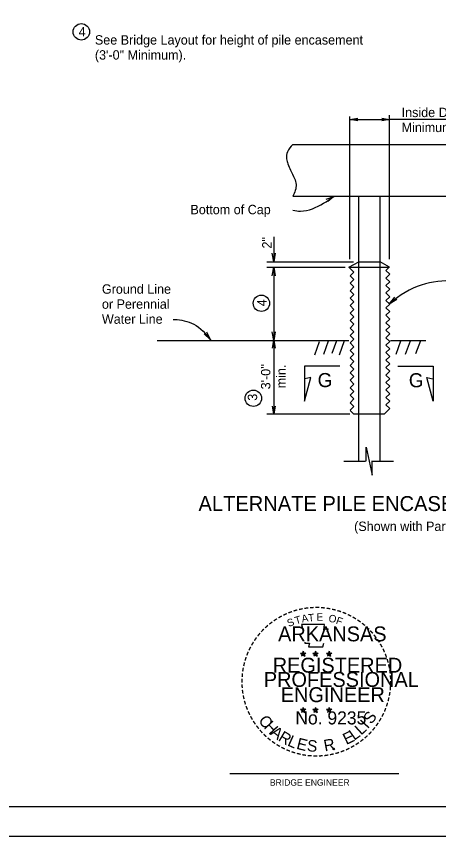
# Model space of a CAD drawing. Extents: x 1053 to 1311, y 5085 to 5337.
# Drawn here: x 1163.9 to 1193.9, y 5085.1 to 5143.4 of the extents above; entities that cross this region are included whole.
import ezdxf

# ---------------------------------------------------------------- set-up
doc = ezdxf.new("R2010")
doc.units = 0
for name, color, linetype in [('1', 7, 'Continuous'), ('2', 7, 'Continuous'), ('7', 7, 'Continuous'), ('9', 7, 'Continuous'), ('B_Border', 7, 'Continuous'), ('B_No_Plot', 7, 'Continuous')]:
    doc.layers.add(name, color=color, linetype=linetype)

msp = doc.modelspace()

# ---------------------------------------------------------------- linework, layer by layer
at = {"layer": '1'}
for p, q in [((1187.562, 5126.114), (1187.562, 5136.252)), ((1187.562, 5136.018), (1190.359, 5136.018)), ((1190.359, 5126.114), (1190.359, 5136.336)), ((1183.514, 5134.241), (1196.697, 5134.241)), ((1183.514, 5130.568), (1196.697, 5130.568)), ((1182.153, 5127.697), (1182.153, 5125.906)), ((1181.658, 5125.906), (1187.801, 5125.906)), ((1181.658, 5125.542), (1187.211, 5125.542)), ((1182.153, 5125.542), (1182.153, 5120.331)), ((1182.162, 5125.496), (1182.162, 5120.286)), ((1182.153, 5120.331), (1182.153, 5115.121)), ((1185.063, 5119.306), (1185.405, 5120.246)), ((1185.704, 5119.349), (1186.046, 5120.289)), ((1186.302, 5119.434), (1186.623, 5120.317)), ((1186.814, 5119.306), (1187.181, 5120.314)), ((1190.829, 5119.349), (1191.171, 5120.289)), ((1191.512, 5119.349), (1191.854, 5120.289)), ((1192.238, 5119.392), (1192.58, 5120.331)), ((1186.834, 5118.507), (1184.334, 5118.507)), ((1184.334, 5118.507), (1184.334, 5116.007)), ((1190.969, 5118.507), (1193.469, 5118.507)), ((1193.469, 5118.507), (1193.469, 5116.007)), ((1184.334, 5116.007), (1184.787, 5117.697)), ((1184.787, 5117.697), (1184.354, 5117.593)), ((1193.469, 5116.007), (1193.016, 5117.697)), ((1193.016, 5117.697), (1193.449, 5117.593)), ((1181.658, 5115.121), (1187.559, 5115.121)), ((1187.806, 5115.121), (1190.017, 5115.121)), ((1188.2, 5111.756), (1188.2, 5115.073)), ((1189.7, 5111.756), (1189.7, 5115.158)), ((1188.699, 5111.742), (1188.699, 5112.742)), ((1188.699, 5112.742), (1189.126, 5110.759)), ((1187.135, 5111.756), (1188.656, 5111.756)), ((1189.083, 5111.756), (1190.658, 5111.756)), ((1189.126, 5110.759), (1189.126, 5111.759)), ((1179.033, 5089.563), (1191.033, 5089.563)), ((1229.529, 5087.179), (1060.921, 5087.179))]:
    msp.add_line(p, q, dxfattribs=at)
for points in [[(1188.109, 5135.922), (1187.562, 5136.018), (1188.109, 5136.115)], [(1189.812, 5136.115), (1190.359, 5136.018), (1189.812, 5135.922)], [(1185.882, 5130.364), (1186.404, 5130.553), (1185.978, 5130.197)], [(1182.262, 5126.522), (1182.153, 5125.906), (1182.045, 5126.522)], [(1182.045, 5124.926), (1182.153, 5125.542), (1182.262, 5124.926)], [(1182.045, 5124.926), (1182.153, 5125.542), (1182.262, 5124.926)], [(1190.878, 5123.229), (1190.346, 5122.902), (1190.734, 5123.392)], [(1177.385, 5120.931), (1177.651, 5120.366), (1177.208, 5120.806)], [(1182.262, 5120.947), (1182.153, 5120.331), (1182.045, 5120.947)], [(1182.057, 5119.784), (1182.153, 5120.331), (1182.25, 5119.784)], [(1182.25, 5115.668), (1182.153, 5115.121), (1182.057, 5115.668)]]:
    msp.add_lwpolyline(points, dxfattribs=at)
for centre in [(1168.493, 5142.256), (1181.274, 5122.967), (1180.703, 5116.22)]:
    msp.add_circle(centre, 0.583, dxfattribs=at)
for points in [[(1183.514, 5134.241), (1183.123, 5133.738), (1183.067, 5133.235), (1183.151, 5132.872), (1183.346, 5132.425), (1183.625, 5131.838), (1183.737, 5131.419), (1183.514, 5130.568)], [(1183.5, 5129.575), (1184.058, 5129.519), (1184.896, 5129.686), (1186.404, 5130.553)]]:
    msp.add_spline(points, degree=3, dxfattribs=at)
at = {"layer": '2'}
msp.add_line((1199.814, 5136.018), (1190.359, 5136.018), dxfattribs=at)
at = {"layer": '7'}
for p, q in [((1188.2, 5125.906), (1188.2, 5130.568)), ((1189.7, 5125.906), (1189.7, 5130.568)), ((1187.475, 5125.542), (1188.201, 5125.906)), ((1187.475, 5125.542), (1190.36, 5125.542)), ((1188.2, 5115.073), (1188.2, 5125.906)), ((1188.201, 5125.906), (1189.701, 5125.906)), ((1189.7, 5115.158), (1189.7, 5125.906)), ((1190.36, 5125.542), (1189.701, 5125.906)), ((1173.886, 5120.331), (1187.478, 5120.331)), ((1190.444, 5120.331), (1192.944, 5120.331))]:
    msp.add_line(p, q, dxfattribs=at)
for points in [[(1187.566, 5124.92), (1187.831, 5125.185), (1187.475, 5125.542)], [(1190.113, 5125.294), (1190.347, 5125.527)], [(1187.566, 5124.39), (1187.831, 5124.655), (1187.566, 5124.92)], [(1190.113, 5124.763), (1190.379, 5125.029), (1190.113, 5125.294)], [(1187.566, 5123.859), (1187.831, 5124.125), (1187.566, 5124.39)], [(1190.113, 5124.233), (1190.379, 5124.498), (1190.113, 5124.763)], [(1187.566, 5123.329), (1187.831, 5123.594), (1187.566, 5123.859)], [(1190.113, 5123.703), (1190.379, 5123.968), (1190.113, 5124.233)], [(1190.113, 5123.172), (1190.379, 5123.437), (1190.113, 5123.703)], [(1187.566, 5122.799), (1187.831, 5123.064), (1187.566, 5123.329)], [(1190.113, 5122.642), (1190.379, 5122.907), (1190.113, 5123.172)], [(1187.566, 5122.268), (1187.831, 5122.534), (1187.566, 5122.799)], [(1190.113, 5122.112), (1190.379, 5122.377), (1190.113, 5122.642)], [(1187.566, 5121.738), (1187.831, 5122.003), (1187.566, 5122.268)], [(1190.113, 5121.581), (1190.379, 5121.846), (1190.113, 5122.112)], [(1187.566, 5121.208), (1187.831, 5121.473), (1187.566, 5121.738)], [(1190.113, 5121.051), (1190.379, 5121.316), (1190.113, 5121.581)], [(1187.566, 5120.677), (1187.831, 5120.943), (1187.566, 5121.208)], [(1190.113, 5120.521), (1190.379, 5120.786), (1190.113, 5121.051)], [(1187.566, 5120.147), (1187.831, 5120.412), (1187.566, 5120.677)], [(1190.113, 5119.99), (1190.379, 5120.255), (1190.113, 5120.521)], [(1187.566, 5119.617), (1187.831, 5119.882), (1187.566, 5120.147)], [(1190.113, 5119.46), (1190.379, 5119.725), (1190.113, 5119.99)], [(1187.566, 5119.086), (1187.831, 5119.352), (1187.566, 5119.617)], [(1187.566, 5118.556), (1187.831, 5118.821), (1187.566, 5119.086)], [(1190.113, 5118.93), (1190.379, 5119.195), (1190.113, 5119.46)], [(1187.566, 5118.026), (1187.831, 5118.291), (1187.566, 5118.556)], [(1190.113, 5118.399), (1190.379, 5118.664), (1190.113, 5118.93)], [(1187.566, 5117.495), (1187.831, 5117.761), (1187.566, 5118.026)], [(1190.113, 5117.869), (1190.379, 5118.134), (1190.113, 5118.399)], [(1187.566, 5116.965), (1187.831, 5117.23), (1187.566, 5117.495)], [(1190.113, 5117.339), (1190.379, 5117.604), (1190.113, 5117.869)], [(1190.113, 5116.808), (1190.379, 5117.073), (1190.113, 5117.339)], [(1187.566, 5116.435), (1187.831, 5116.7), (1187.566, 5116.965)], [(1190.113, 5116.278), (1190.379, 5116.543), (1190.113, 5116.808)], [(1187.566, 5115.904), (1187.831, 5116.17), (1187.566, 5116.435)], [(1190.113, 5115.748), (1190.379, 5116.013), (1190.113, 5116.278)], [(1187.566, 5115.374), (1187.831, 5115.639), (1187.566, 5115.904)], [(1190.017, 5115.121), (1190.379, 5115.482), (1190.113, 5115.748)], [(1187.806, 5115.121), (1187.576, 5115.35)]]:
    msp.add_lwpolyline(points, dxfattribs=at)
for points in [[(1194.915, 5124.574), (1194.211, 5124.598), (1192.57, 5124.406), (1191.128, 5123.597), (1190.346, 5122.902)], [(1175.021, 5121.821), (1175.365, 5121.826), (1176.365, 5121.679), (1177.183, 5121.031), (1177.651, 5120.366)]]:
    msp.add_open_spline(points, degree=3, dxfattribs=at)
at = {"layer": 'B_Border'}
for p, q in [((1184.046, 5098.113), (1184.35, 5097.889)), ((1184.046, 5098.113), (1184.425, 5098.113)), ((1184.238, 5098.246), (1184.121, 5097.889)), ((1184.425, 5098.113), (1184.121, 5097.889)), ((1184.238, 5098.246), (1184.35, 5097.889)), ((1184.932, 5098.113), (1185.236, 5097.889)), ((1184.932, 5098.113), (1185.31, 5098.113)), ((1185.124, 5098.246), (1185.006, 5097.889)), ((1185.31, 5098.113), (1185.006, 5097.889)), ((1185.124, 5098.246), (1185.236, 5097.889)), ((1185.886, 5098.113), (1186.19, 5097.889)), ((1185.886, 5098.113), (1186.265, 5098.113)), ((1186.078, 5098.246), (1185.961, 5097.889)), ((1186.265, 5098.113), (1185.961, 5097.889)), ((1186.078, 5098.246), (1186.19, 5097.889)), ((1184.046, 5094.118), (1184.35, 5093.894)), ((1184.046, 5094.118), (1184.425, 5094.118)), ((1184.238, 5094.251), (1184.121, 5093.894)), ((1184.425, 5094.118), (1184.121, 5093.894)), ((1184.238, 5094.251), (1184.35, 5093.894)), ((1184.932, 5094.118), (1185.236, 5093.894)), ((1184.932, 5094.118), (1185.31, 5094.118)), ((1185.124, 5094.251), (1185.006, 5093.894)), ((1185.31, 5094.118), (1185.006, 5093.894)), ((1185.124, 5094.251), (1185.236, 5093.894)), ((1185.886, 5094.118), (1186.19, 5093.894)), ((1185.886, 5094.118), (1186.265, 5094.118)), ((1186.078, 5094.251), (1185.961, 5093.894)), ((1186.265, 5094.118), (1185.961, 5093.894)), ((1186.078, 5094.251), (1186.19, 5093.894))]:
    msp.add_line(p, q, dxfattribs=at)
for points in [[(1184.11, 5100.15), (1184.238, 5099.707)], [(1185.95, 5099.643), (1186.014, 5099.835), (1185.694, 5099.771), (1185.758, 5100.15), (1184.11, 5100.15)], [(1184.361, 5098.881), (1184.361, 5098.817), (1184.681, 5098.817), (1184.617, 5098.566), (1185.63, 5098.566), (1185.694, 5098.817)]]:
    msp.add_lwpolyline(points, dxfattribs=at)
msp.add_circle((1186.412, 5091.29), 0.0503, dxfattribs=at)
for centre, radius, start, end in [((1186.407, 5091.29), 0.0483, 278.17502, 85.49463), ((1186.392, 5091.289), 0.0518, 294.00117, 69.66848)]:
    msp.add_arc(centre, radius, start, end, dxfattribs=at)
at = {"layer": 'B_No_Plot'}
msp.add_lwpolyline([(1053.308, 5198.862), (1231.974, 5198.862), (1231.974, 5085.07), (1053.308, 5085.07)], close=True, dxfattribs=at)

# ---------------------------------------------------------------- texts
at = {"layer": '1'}
for s, height, p in [('4', 0.667, (1168.302, 5141.931)), ('Bottom of Cap', 0.66667, (1176.237, 5129.295)), ('Ground Line ', 0.66658, (1169.953, 5123.646)), ('or Perennial  ', 0.66658, (1169.953, 5122.579)), ('Water Line', 0.6666, (1169.953, 5121.512)), ('G', 1, (1185.265, 5117.011)), ('G', 1, (1191.737, 5116.999)), ('BRIDGE ENGINEER', 0.45328, (1181.881, 5088.688))]:
    msp.add_text(s, height=height, dxfattribs=at).set_placement(p)
for s, height, p in [('2"', 0.6666, (1181.993, 5126.859)), ('4', 0.667, (1181.636, 5122.755)), ("3'-0''", 0.6666, (1181.912, 5116.851)), ('min.', 0.6667, (1183.002, 5116.922)), ('3', 0.667, (1180.973, 5116.044))]:
    msp.add_text(s, height=height, rotation=90, dxfattribs=at).set_placement(p)
at = {"layer": '7'}
for s, height, p in [('See Bridge Layout for height of pile encasement ', 0.66667, (1169.455, 5141.35)), ('(3\'-0" Minimum).', 0.66667, (1169.455, 5140.283)), ('ALTERNATE PILE ENCASEMENT DETAIL FOR STEEL SHELL PILES', 1.067, (1176.807, 5108.201)), ('(Shown with Partial   Height Encasement)', 0.66658, (1187.856, 5106.787))]:
    msp.add_text(s, height=height, dxfattribs=at).set_placement(p)
at = {"layer": '9'}
for s, p in [('Inside Diameter', (1191.228, 5136.199)), ("Minimum = ''D'' + 8''", (1191.228, 5135.133))]:
    msp.add_text(s, height=0.66667, dxfattribs=at).set_placement(p)
at = {"layer": 'B_Border'}
for s, height, rotation, p in [('-', 0.842, 21.4285, (1183.257, 5100.641)), ('-', 0.842, 17.1428, (1183.604, 5100.774)), ('-', 0.843, 12.8571, (1183.961, 5100.875)), ('-', 0.843, 8.5714, (1184.324, 5100.955)), ('-', 0.843, 4.2857, (1184.692, 5101.003)), ('-', 0.843, 355.7131, (1185.428, 5101.019)), ('-', 0.843, 351.4274, (1185.801, 5100.987)), ('-', 0.843, 347.1417, (1186.164, 5100.923)), ('-', 0.843, 342.856, (1186.521, 5100.838)), ('-', 0.843, 338.5703, (1186.878, 5100.726)), ('-', 0.843, 34.2856, (1182.292, 5100.102)), ('-', 0.843, 29.9999, (1182.601, 5100.305)), ('-', 0.843, 25.7142, (1182.921, 5100.486)), ('S', 0.528, 21.59401, (1183.22, 5099.958)), ('T', 0.528, 16.4036, (1183.726, 5100.15)), ('A', 0.529, 11.21318, (1184.174, 5100.278)), ('T', 0.529, 6.02276, (1184.617, 5100.342)), ('E', 0.529, 0.83234, (1185.188, 5100.406)), ('O', 0.528, 350.4515, (1186.014, 5100.342)), ('F', 0.528, 340.07066, (1186.521, 5100.214)), ('-', 0.843, 334.2846, (1187.22, 5100.582)), ('-', 0.843, 329.9989, (1187.55, 5100.417)), ('-', 0.843, 325.7132, (1187.865, 5100.23)), ('-', 0.843, 47.1427, (1181.465, 5099.361)), ('-', 0.843, 42.857, (1181.721, 5099.627)), ('-', 0.843, 38.5713, (1181.998, 5099.873)), ('-', 0.843, 321.4275, (1188.169, 5100.017)), ('-', 0.843, 317.1418, (1188.457, 5099.782)), ('-', 0.843, 55.7141, (1181.017, 5098.769)), ('-', 0.843, 51.4284, (1181.23, 5099.073)), ('-', 0.843, 312.8561, (1188.724, 5099.526)), ('-', 0.843, 308.5704, (1188.969, 5099.249)), ('-', 0.843, 59.9998, (1180.83, 5098.454)), ('-', 0.843, 304.2847, (1189.198, 5098.955)), ('-', 0.843, 299.999, (1189.401, 5098.646)), ('-', 0.843, 68.5712, (1180.521, 5097.777)), ('-', 0.843, 64.2855, (1180.665, 5098.123)), ('-', 0.843, 295.7133, (1189.582, 5098.326)), ('-', 0.843, 291.4276, (1189.737, 5097.99)), ('-', 0.843, 72.8569, (1180.409, 5097.425)), ('-', 0.843, 287.1419, (1189.87, 5097.643)), ('-', 0.843, 81.4283, (1180.26, 5096.705)), ('-', 0.843, 77.1426, (1180.324, 5097.067)), ('-', 0.843, 282.8562, (1189.972, 5097.286)), ('-', 0.843, 278.5705, (1190.052, 5096.923)), ('-', 0.843, 85.714, (1180.228, 5096.331)), ('-', 0.843, 274.2848, (1190.1, 5096.555)), ('-', 0.843, 94.2854, (1180.244, 5095.595)), ('-', 0.842, 89.9997, (1180.222, 5095.963)), ('-', 0.843, 265.7134, (1190.116, 5095.819)), ('-', 0.842, 269.9991, (1190.121, 5096.187)), ('-', 0.843, 98.5711, (1180.292, 5095.227)), ('-', 0.843, 261.4277, (1190.084, 5095.446)), ('-', 0.843, 102.8568, (1180.372, 5094.865)), ('-', 0.843, 107.1425, (1180.473, 5094.507)), ('-', 0.843, 252.8563, (1189.934, 5094.726)), ('-', 0.843, 257.142, (1190.02, 5095.083)), ('-', 0.843, 111.4282, (1180.606, 5094.161)), ('-', 0.843, 115.7139, (1180.761, 5093.825)), ('-', 0.843, 248.5706, (1189.822, 5094.369)), ('-', 0.843, 119.9996, (1180.942, 5093.505)), ('C', 0.816, 306.32361, (1181.023, 5093.322)), ('S', 0.816, 52.99221, (1189.08, 5093.007)), ('-', 0.843, 239.9992, (1189.513, 5093.697)), ('-', 0.843, 244.2849, (1189.678, 5094.027)), ('-', 0.843, 124.2853, (1181.145, 5093.195)), ('-', 0.843, 128.571, (1181.374, 5092.902)), ('H', 0.816, 312.85775, (1181.402, 5092.828)), ('A', 0.816, 323.49499, (1181.85, 5092.34)), ('L', 0.816, 42.18869, (1188.347, 5092.237)), ('I', 0.816, 47.56769, (1188.809, 5092.689)), ('-', 0.843, 231.4278, (1189.113, 5093.078)), ('-', 0.843, 235.7135, (1189.326, 5093.382)), ('-', 0.843, 132.8567, (1181.62, 5092.625)), ('-', 0.843, 137.1424, (1181.886, 5092.369)), ('R', 0.816, 329.2213, (1182.412, 5091.926)), ('L', 0.816, 335.93892, (1183.07, 5091.563)), ('E', 0.816, 25.81061, (1187.302, 5091.575)), ('L', 0.816, 35.44481, (1187.857, 5091.873)), ('-', 0.843, 222.8564, (1188.622, 5092.523)), ('-', 0.843, 227.1421, (1188.878, 5092.79)), ('-', 0.843, 141.4281, (1182.174, 5092.134)), ('-', 0.843, 145.7138, (1182.478, 5091.921)), ('-', 0.843, 149.9995, (1182.793, 5091.734)), ('E', 0.816, 345.69245, (1183.713, 5091.317)), ('S', 0.816, 353.99643, (1184.481, 5091.149)), ('R', 0.816, 10.74399, (1185.78, 5091.12)), ('-', 0.843, 214.285, (1188.052, 5092.049)), ('-', 0.843, 218.5707, (1188.345, 5092.278)), ('-', 0.843, 154.2852, (1183.124, 5091.569)), ('-', 0.842, 158.5709, (1183.47, 5091.425)), ('-', 0.843, 162.8566, (1183.822, 5091.313)), ('-', 0.843, 197.1422, (1186.74, 5091.377)), ('-', 0.843, 201.4279, (1187.086, 5091.51)), ('-', 0.843, 205.7136, (1187.422, 5091.665)), ('-', 0.843, 209.9993, (1187.742, 5091.846)), ('-', 0.843, 167.1423, (1184.18, 5091.227)), ('-', 0.843, 171.428, (1184.542, 5091.163)), ('-', 0.843, 175.7137, (1184.916, 5091.131)), ('-', 0.843, 179.9994, (1185.284, 5091.126)), ('-', 0.843, 184.2851, (1185.652, 5091.147)), ('-', 0.843, 188.5708, (1186.02, 5091.195)), ('-', 0.843, 192.8565, (1186.382, 5091.275))]:
    msp.add_text(s, height=height, rotation=rotation, dxfattribs=at).set_placement(p)
for s, height, p in [('-', 0.843, (1185.06, 5101.025)), ('ARKANSAS', 1.0575, (1182.457, 5098.945)), ('REGISTERED', 1.0575, (1182.078, 5096.721)), ('PROFESSIONAL', 1.05754, (1181.444, 5095.707)), ('ENGINEER', 1.0575, (1182.649, 5094.625)), ('No. 9235', 0.928, (1183.684, 5093.041))]:
    msp.add_text(s, height=height, dxfattribs=at).set_placement(p)

doc.saveas('drawing.dxf')
